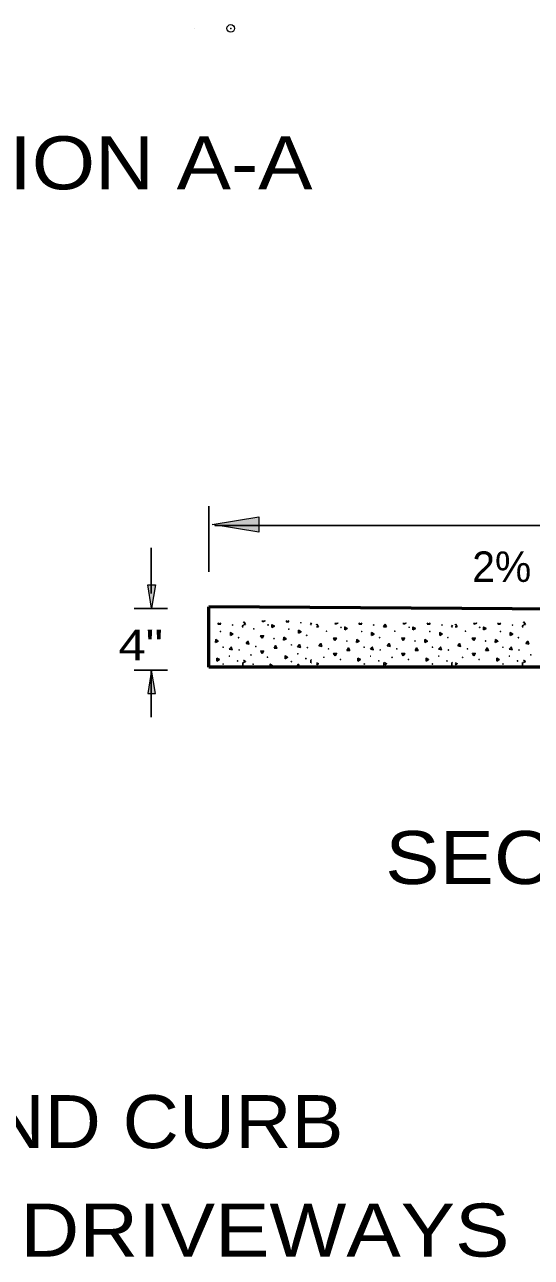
# Model space of a CAD drawing. Extents: x 75.6 to 110.9, y 28 to 50.
# Drawn here: x 98.089 to 100.105, y 33.984 to 38.889 of the extents above; entities that cross this region are included whole.
import ezdxf
from ezdxf.enums import TextEntityAlignment as Align

# ---------------------------------------------------------------- set-up
doc = ezdxf.new("R2010")
doc.units = 0
doc.header["$LTSCALE"] = 0.06
doc.header["$PDMODE"] = 32
doc.header["$PDSIZE"] = 0.03
doc.layers.add('1', color=7, linetype='Continuous', lineweight=25)
doc.layers.add('3', color=7, linetype='Continuous', lineweight=13)

msp = doc.modelspace()

# ---------------------------------------------------------------- hatches: boundary and pattern name
at = {"layer": '3'}
for points in [[(99.02008, 36.9305), (99.02008, 36.86892), (98.8355, 36.89975), (98.8355, 36.89975)], [(98.57875, 36.65958), (98.60942, 36.65958), (98.59408, 36.56733), (98.59408, 36.56733)], [(98.57875, 36.22733), (98.60942, 36.22733), (98.59408, 36.31958), (98.59408, 36.31958)]]:
    msp.add_hatch(color=256, dxfattribs=at).paths.add_polyline_path(points)

# ---------------------------------------------------------------- linework, layer by layer
at = {"layer": '1', "lineweight": 53}
for p, q in [((98.82217, 36.33233), (98.82217, 36.57225)), ((102.10992, 36.55025), (98.82217, 36.57225)), ((102.13775, 36.33233), (98.82217, 36.33233))]:
    msp.add_line(p, q, dxfattribs=at)
at = {"layer": '1'}
for p, q in [((98.86092, 36.50833), (98.85758, 36.50258)), ((98.85758, 36.50258), (98.86925, 36.50258)), ((98.86925, 36.50258), (98.86592, 36.50833)), ((98.95867, 36.4995), (98.95475, 36.49267)), ((98.95475, 36.49267), (98.95867, 36.49267)), ((98.962, 36.51208), (98.96008, 36.50883)), ((98.96008, 36.502), (98.96775, 36.502)), ((98.96775, 36.502), (98.962, 36.51208)), ((99.03533, 36.51767), (99.03458, 36.51308)), ((99.03458, 36.51308), (99.0455, 36.51708)), ((99.0455, 36.51708), (99.04475, 36.51767)), ((99.13233, 36.51767), (99.129, 36.51192)), ((99.129, 36.51192), (99.14067, 36.51192)), ((99.14067, 36.51192), (99.13733, 36.51767)), ((99.23008, 36.50883), (99.22617, 36.502)), ((99.22617, 36.502), (99.23008, 36.502)), ((99.25208, 36.50275), (99.25017, 36.4995)), ((99.25017, 36.49267), (99.25783, 36.49267)), ((99.25783, 36.49267), (99.25208, 36.50275)), ((99.32542, 36.50833), (99.32467, 36.50375)), ((99.32467, 36.50375), (99.33558, 36.50775)), ((99.33558, 36.50775), (99.33483, 36.50833)), ((99.42242, 36.50833), (99.41908, 36.50258)), ((99.41908, 36.50258), (99.43075, 36.50258)), ((99.43075, 36.50258), (99.42742, 36.50833)), ((99.52017, 36.4995), (99.51625, 36.49267)), ((99.51625, 36.49267), (99.52017, 36.49267)), ((99.5235, 36.50275), (99.52158, 36.4995)), ((99.52158, 36.49267), (99.52925, 36.49267)), ((99.52925, 36.49267), (99.5235, 36.50275)), ((99.59683, 36.50833), (99.59608, 36.50375)), ((99.59608, 36.50375), (99.607, 36.50775)), ((99.607, 36.50775), (99.60625, 36.50833)), ((99.69383, 36.50833), (99.6905, 36.50258)), ((99.6905, 36.50258), (99.70217, 36.50258)), ((99.70217, 36.50258), (99.69883, 36.50833)), ((99.79158, 36.4995), (99.78767, 36.49267)), ((99.78767, 36.49267), (99.79158, 36.49267)), ((99.80433, 36.50275), (99.80242, 36.4995)), ((99.80242, 36.49267), (99.81008, 36.49267)), ((99.81008, 36.49267), (99.80433, 36.50275)), ((99.87767, 36.50833), (99.87692, 36.50375)), ((99.87692, 36.50375), (99.88783, 36.50775)), ((99.88783, 36.50775), (99.88708, 36.50833)), ((99.97467, 36.50833), (99.97133, 36.50258)), ((99.97133, 36.50258), (99.983, 36.50258)), ((99.983, 36.50258), (99.97967, 36.50833)), ((100.07242, 36.4995), (100.0685, 36.49267)), ((100.0685, 36.49267), (100.07242, 36.49267)), ((100.07575, 36.51208), (100.07383, 36.50883)), ((100.07383, 36.502), (100.0815, 36.502)), ((100.0815, 36.502), (100.07575, 36.51208)), ((98.95633, 36.35133), (98.95633, 36.33967)), ((98.95633, 36.35133), (98.95633, 36.33967)), ((98.95867, 36.35), (98.95633, 36.35133)), ((98.95867, 36.35), (98.95633, 36.35133)), ((99.22775, 36.36067), (99.22775, 36.349)), ((99.22775, 36.36067), (99.22775, 36.349)), ((99.23008, 36.35933), (99.22775, 36.36067)), ((99.23008, 36.35933), (99.22775, 36.36067)), ((99.22775, 36.349), (99.23008, 36.35033)), ((99.22775, 36.349), (99.23008, 36.35033)), ((99.51783, 36.35133), (99.51783, 36.33967)), ((99.51783, 36.35133), (99.51783, 36.33967)), ((99.52017, 36.35), (99.51783, 36.35133)), ((99.52017, 36.35), (99.51783, 36.35133)), ((99.78925, 36.35133), (99.78925, 36.33967)), ((99.78925, 36.35133), (99.78925, 36.33967)), ((99.79158, 36.35), (99.78925, 36.35133)), ((99.79158, 36.35), (99.78925, 36.35133)), ((100.07008, 36.35133), (100.07008, 36.33967)), ((100.07008, 36.35133), (100.07008, 36.33967)), ((100.07242, 36.35), (100.07008, 36.35133)), ((100.07242, 36.35), (100.07008, 36.35133)), ((98.95633, 36.33967), (98.95867, 36.341)), ((98.95633, 36.33967), (98.95867, 36.341)), ((99.51783, 36.33967), (99.52017, 36.341)), ((99.51783, 36.33967), (99.52017, 36.341)), ((99.78925, 36.33967), (99.79158, 36.341)), ((99.78925, 36.33967), (99.79158, 36.341)), ((100.07008, 36.33967), (100.07242, 36.341)), ((100.07008, 36.33967), (100.07242, 36.341))]:
    msp.add_line(p, q, dxfattribs=at)
for points in [[(99.0725, 36.48942), (99.08258, 36.49533), (99.07258, 36.50117)], [(99.36258, 36.48008), (99.37267, 36.486), (99.36267, 36.49183)], [(99.634, 36.48008), (99.64408, 36.486), (99.63408, 36.49183)], [(99.91483, 36.48008), (99.92492, 36.486), (99.91492, 36.49183)], [(98.84783, 36.43), (98.85833, 36.435), (98.84892, 36.44167)], [(98.90742, 36.45783), (98.91758, 36.46367), (98.90758, 36.4695)], [(99.03358, 36.447), (99.03933, 36.457), (99.02775, 36.457)], [(99.11925, 36.43933), (99.12975, 36.44433), (99.12033, 36.451)], [(99.17883, 36.46717), (99.189, 36.473), (99.179, 36.47883)], [(99.32367, 36.43767), (99.32942, 36.44767), (99.31783, 36.44767)], [(99.40933, 36.43), (99.41983, 36.435), (99.41042, 36.44167)], [(99.46892, 36.45783), (99.47908, 36.46367), (99.46908, 36.4695)], [(99.59508, 36.43767), (99.60083, 36.44767), (99.58925, 36.44767)], [(99.68075, 36.43), (99.69125, 36.435), (99.68183, 36.44167)], [(99.74033, 36.45783), (99.7505, 36.46367), (99.7405, 36.4695)], [(99.87592, 36.43767), (99.88167, 36.44767), (99.87008, 36.44767)], [(99.96158, 36.43), (99.97208, 36.435), (99.96267, 36.44167)], [(100.02117, 36.45783), (100.03133, 36.46367), (100.02133, 36.4695)], [(98.90292, 36.40342), (98.91442, 36.40142), (98.9105, 36.41233)], [(98.96975, 36.42617), (98.98125, 36.42417), (98.97733, 36.435)], [(99.034, 36.38608), (99.03983, 36.39617), (99.02817, 36.39617)], [(99.081, 36.40808), (99.09258, 36.40808), (99.08675, 36.41817)], [(99.17433, 36.41275), (99.18583, 36.41075), (99.18192, 36.42167)], [(99.25983, 36.41683), (99.27133, 36.41483), (99.26742, 36.42567)], [(99.37108, 36.39875), (99.38267, 36.39875), (99.37683, 36.40883)], [(99.46442, 36.40342), (99.47592, 36.40142), (99.472, 36.41233)], [(99.53125, 36.41683), (99.54275, 36.41483), (99.53883, 36.42567)], [(99.6425, 36.39875), (99.65408, 36.39875), (99.64825, 36.40883)], [(99.73583, 36.40342), (99.74733, 36.40142), (99.74342, 36.41233)], [(99.81208, 36.41683), (99.82358, 36.41483), (99.81967, 36.42567)], [(99.92333, 36.39875), (99.93492, 36.39875), (99.92908, 36.40883)], [(100.01667, 36.40342), (100.02817, 36.40142), (100.02425, 36.41233)], [(100.0835, 36.42617), (100.095, 36.42417), (100.09108, 36.435)], [(98.8535, 36.35625), (98.86358, 36.362), (98.85358, 36.36783)], [(99.12492, 36.36558), (99.135, 36.37133), (99.125, 36.37717)], [(99.32408, 36.37675), (99.32992, 36.38683), (99.31825, 36.38683)], [(99.415, 36.35625), (99.42508, 36.362), (99.41508, 36.36783)], [(99.5955, 36.37675), (99.60133, 36.38683), (99.58967, 36.38683)], [(99.68642, 36.35625), (99.6965, 36.362), (99.6865, 36.36783)], [(99.87633, 36.37675), (99.88217, 36.38683), (99.8705, 36.38683)], [(99.96725, 36.35625), (99.97733, 36.362), (99.96733, 36.36783)]]:
    msp.add_lwpolyline(points, close=True, dxfattribs=at)
for points in [[(98.82108, 36.39875), (98.82117, 36.39875), (98.82108, 36.39892)], [(98.96008, 36.35033), (98.96783, 36.35483), (98.96008, 36.35933)], [(99.07467, 36.33717), (99.06575, 36.34467), (99.06375, 36.33317)], [(99.18333, 36.3335), (99.1775, 36.34358), (99.17167, 36.3335)], [(99.25017, 36.341), (99.25792, 36.3455), (99.25017, 36.35)], [(99.52158, 36.341), (99.52933, 36.3455), (99.52158, 36.35)], [(99.80242, 36.341), (99.81017, 36.3455), (99.80242, 36.35)], [(100.07383, 36.35033), (100.08158, 36.35483), (100.07383, 36.35933)]]:
    msp.add_lwpolyline(points, dxfattribs=at)
for centre in [(98.91648, 36.49975), (99.05737, 36.50015), (99.1879, 36.50908), (99.34746, 36.49082), (99.47798, 36.49975), (99.61887, 36.49082), (99.7494, 36.49975), (99.89971, 36.49082), (100.03023, 36.49975), (98.86851, 36.4741), (98.93992, 36.44955), (99.00047, 36.48454), (99.0808, 36.4455), (99.13993, 36.48343), (99.21134, 36.45889), (99.29055, 36.4752), (99.43001, 36.4741), (99.50142, 36.44955), (99.56197, 36.4752), (99.70143, 36.4741), (99.77284, 36.44955), (99.8428, 36.4752), (99.98226, 36.4741), (100.05367, 36.44955), (98.87857, 36.41162), (98.94215, 36.40046), (99.0083, 36.41425), (99.14998, 36.42095), (99.21357, 36.40979), (99.29838, 36.40491), (99.37088, 36.43616), (99.44007, 36.41162), (99.50365, 36.40046), (99.5698, 36.40491), (99.6423, 36.43616), (99.71148, 36.41162), (99.77507, 36.40046), (99.85063, 36.40491), (99.92313, 36.43616), (99.99232, 36.41162), (100.0559, 36.40046), (98.87857, 36.34468), (98.90422, 36.37591), (98.93657, 36.35694), (98.98933, 36.38079), (98.99824, 36.34398), (99.05515, 36.37186), (99.14998, 36.35401), (99.17563, 36.38524), (99.20799, 36.36628), (99.27942, 36.37145), (99.34523, 36.36252), (99.44007, 36.34468), (99.46572, 36.37591), (99.49807, 36.35694), (99.55083, 36.37145), (99.61665, 36.36252), (99.71148, 36.34468), (99.73713, 36.37591), (99.76949, 36.35694), (99.83167, 36.37145), (99.89748, 36.36252), (99.99232, 36.34468), (100.01797, 36.37591), (100.05032, 36.35694), (100.10308, 36.38079)]:
    msp.add_circle(centre, 0.000647, dxfattribs=at)
at = {"layer": '3'}
msp.add_line((98.76375, 38.87358), (98.76383, 38.87358), dxfattribs=at)
at = {"layer": '3', "lineweight": 25}
for p, q in [((98.82217, 36.71158), (98.82217, 36.97308)), ((102.41458, 36.89625), (98.84517, 36.89625)), ((98.59225, 36.62467), (98.59225, 36.8075)), ((98.52475, 36.56558), (98.65775, 36.56558)), ((98.52475, 36.32058), (98.65775, 36.32058)), ((98.59225, 36.31558), (98.59225, 36.13283))]:
    msp.add_line(p, q, dxfattribs=at)
at = {"layer": '3'}
for points in [[(99.02008, 36.9305), (99.02008, 36.86892), (98.8355, 36.89975), (98.8355, 36.89975)], [(98.57875, 36.65958), (98.60942, 36.65958), (98.59408, 36.56733), (98.59408, 36.56733)], [(98.57875, 36.22733), (98.60942, 36.22733), (98.59408, 36.31958), (98.59408, 36.31958)]]:
    msp.add_lwpolyline(points, close=True, dxfattribs=at)
msp.add_point((98.90858, 38.87358), dxfattribs=at)

# ---------------------------------------------------------------- texts
at = {"layer": '1'}
for s, height, width, p in [('SECTION A-A', 0.2109, 1.15, (98.198, 38.23342)), ('4"', 0.1215, 1.2, (98.55071, 36.35925)), ('SECTION C-C', 0.2109, 1.15, (100.57754, 35.46933)), ('SIDEWALK AND CURB', 0.2109, 1.1, (97.70254, 34.41842)), ('TREATMENT AT DRIVEWAYS', 0.2109, 1.15, (97.7565, 33.98692))]:
    msp.add_text(s, height=height, dxfattribs=dict(at, width=width)).set_placement(p, align=Align.CENTER)
msp.add_text('2%', height=0.1215, dxfattribs=at).set_placement((99.98742, 36.67108), align=Align.CENTER)

doc.saveas('drawing.dxf')
